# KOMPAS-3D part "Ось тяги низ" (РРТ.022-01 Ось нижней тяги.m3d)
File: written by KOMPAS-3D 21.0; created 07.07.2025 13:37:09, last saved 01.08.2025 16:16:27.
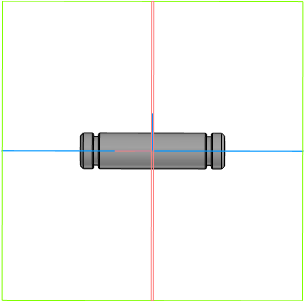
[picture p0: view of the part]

Document properties: Автор: User; Полное имя файла: C:\Users\User\Desktop\Ручной ротатор КД\Модели КД\РРТ.022-01 Ось нижней тяги.m3d

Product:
- Part/product: Ось тяги низ
    Масса: 0.005156
    Форматы листов документа: A4

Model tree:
1. Эскиз:1
2. Элемент выдавливания:1
     Расстояние 1 = 24
3. Фаска:1  (with: Элемент выдавливания:1)
     Угол = 45; Длина 1 = 0.5; Длина 2 = 0.5
4. Эскиз:2  (with: Элемент выдавливания:1)
5. Элемент вращения:1  (with: Элемент выдавливания:1)
     Угол 1 = 360
6. Фаска:2  (with: Элемент вращения:1)
     Угол = 45; Длина 1 = 0.2; Длина 2 = 0.2

Expressions: 4.8/2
